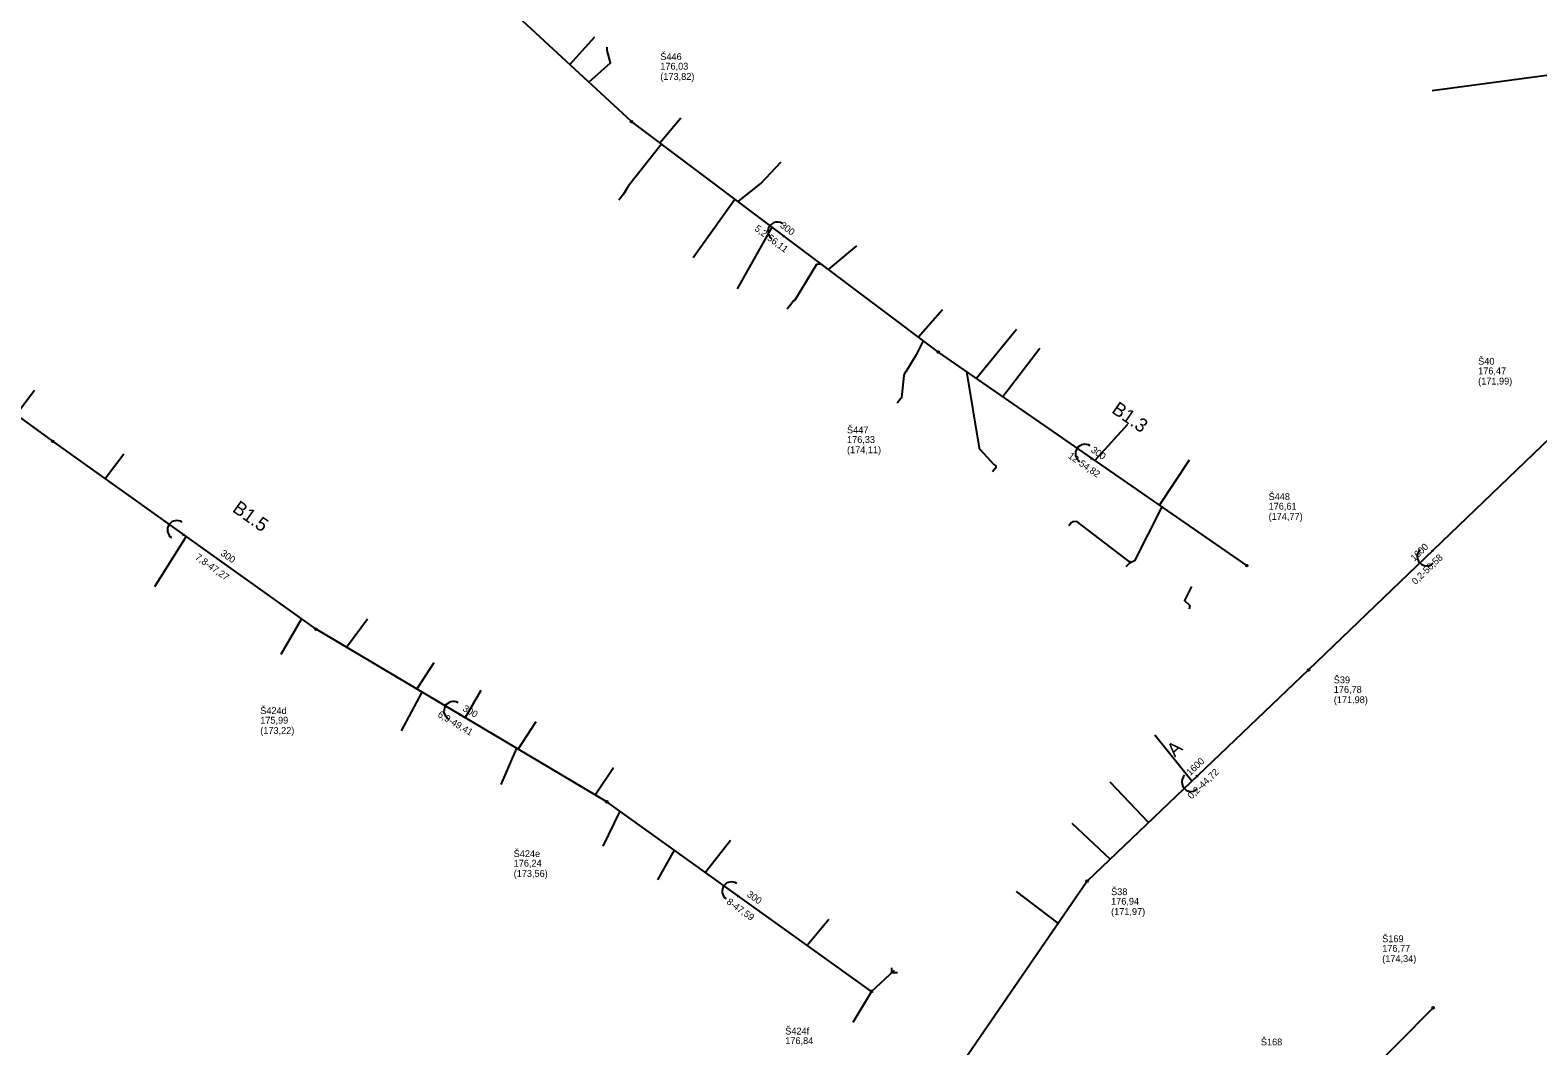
# Model space of a CAD drawing. Extents: x -548529 to -543591, y -1201432 to -1192608.
# Drawn here: x -544687.6 to -544467.3, y -1193181.6 to -1193033.2 of the extents above; entities that cross this region are included whole.
import ezdxf

# ---------------------------------------------------------------- set-up
doc = ezdxf.new("R2010")
doc.units = 0
for name, color, linetype in [('C3D_Bod-Značky', 7, 'Continuous'), ('C3D_Koridor', 7, 'Continuous'), ('C3D_Křižovatka', 7, 'Continuous'), ('C3D_Netisknutelná', 7, 'Continuous'), ('C3D_PP-zobrazeni v PR', 7, 'Continuous'), ('C3D_PR-Popisek', 7, 'Continuous'), ('C3D_SPR-Popisek', 7, 'Continuous'), ('C3D_Tlakove_potrubi_Popis', 7, 'Continuous'), ('C3D_ZPR-Formaty', 7, 'Continuous')]:
    doc.layers.add(name, color=color, linetype=linetype)

# ---------------------------------------------------------------- blocks, each defined once
blk = doc.blocks.new('100')
at = {"layer": 'Defpoints'}
blk.add_circle((0, 0), 0.127, dxfattribs=at)
blk = doc.blocks.new('91')
at = {"layer": 'Defpoints'}
blk.add_lwpolyline([(0.08, 0.14), (0.19, 0), (0.08, -0.14)], dxfattribs=at)
blk.add_arc((1.37, 0), 1.37, 270, 90, dxfattribs=at)

msp = doc.modelspace()

# ---------------------------------------------------------------- linework, layer by layer
at = {"layer": 'C3D_Bod-Značky'}
for points in [[(-544599.74, -1193046.54), (-544648.06, -1193001.85)], [(-544554.87, -1193080.23), (-544599.74, -1193046.54)], [(-544684.29, -1193093.27), (-544727.17, -1193062.03)], [(-544509.8, -1193111.44), (-544554.87, -1193080.23)], [(-544645.82, -1193120.74), (-544684.29, -1193093.27)], [(-544464.291, -1193091.64), (-544500.765, -1193126.682)], [(-544603.33, -1193145.96), (-544645.82, -1193120.74)], [(-544500.765, -1193126.682), (-544533.129, -1193157.543)], [(-544564.63, -1193173.66), (-544603.33, -1193145.96)], [(-544533.129, -1193157.543), (-544575.082, -1193218.62)], [(-544482.566, -1193176.062), (-544498.256, -1193191.91)]]:
    msp.add_lwpolyline(points, dxfattribs=at)
at = {"layer": 'C3D_Koridor'}
for points in [[(-544608.748, -1193038.209), (-544605.076, -1193034.138)], [(-544605.957, -1193040.79), (-544602.81, -1193037.965), (-544603.28, -1193036.152), (-544603.255, -1193035.67)], [(-544460.152, -1193039.016), (-544482.684, -1193042.051)], [(-544595.59, -1193049.656), (-544592.531, -1193045.973)], [(-544595.334, -1193049.848), (-544600.16, -1193055.92)], [(-544584.154, -1193058.242), (-544580.83, -1193055.57), (-544577.861, -1193052.437)], [(-544600.16, -1193055.92), (-544600.87, -1193057.14), (-544601.577, -1193058.049)], [(-544584.602, -1193057.906), (-544590.733, -1193066.461)], [(-544579.204, -1193061.959), (-544584.3, -1193070.962)], [(-544570.952, -1193068.155), (-544566.769, -1193064.702)], [(-544572.015, -1193067.357), (-544572.7, -1193067.43), (-544575.85, -1193072.65)], [(-544575.85, -1193072.65), (-544576.09, -1193072.8), (-544576.28, -1193073.07), (-544576.63, -1193073.51), (-544576.98, -1193073.97)], [(-544557.805, -1193078.026), (-544554.281, -1193073.989)], [(-544549.328, -1193084.068), (-544543.432, -1193076.86)], [(-544557.077, -1193078.573), (-544558.14, -1193080.61), (-544559.64, -1193083.12), (-544559.81, -1193083.35)], [(-544545.472, -1193086.738), (-544540.02, -1193079.651)], [(-544559.81, -1193083.35), (-544559.94, -1193083.63), (-544560.26, -1193086.91), (-544560.35, -1193087.01), (-544560.891, -1193087.694)], [(-544550.753, -1193083.085), (-544548.89, -1193094.27)], [(-544689.665, -1193089.354), (-544686.981, -1193085.778)], [(-544532.022, -1193096.052), (-544527.177, -1193090.745)], [(-544676.662, -1193098.717), (-544673.901, -1193095.117)], [(-544548.89, -1193094.27), (-544548.77, -1193094.48), (-544546.79, -1193096.66)], [(-544522.568, -1193102.599), (-544518.155, -1193095.988)], [(-544546.79, -1193096.66), (-544546.46, -1193096.84), (-544546.46, -1193097.05), (-544546.49, -1193097.15), (-544546.965, -1193097.744)], [(-544522.224, -1193102.838), (-544526.21, -1193110.74), (-544526.59, -1193110.95)], [(-544526.59, -1193110.95), (-544526.98, -1193110.81), (-544534.64, -1193105.01), (-544535.25, -1193105.04), (-544535.4, -1193105.15), (-544535.79, -1193105.611)], [(-544664.785, -1193107.198), (-544669.433, -1193114.52)], [(-544526.59, -1193110.95), (-544527.05, -1193111.17), (-544527.497, -1193111.63)], [(-544517.89, -1193114.48), (-544518.89, -1193116.54), (-544518.12, -1193117.24), (-544518.201, -1193117.804)], [(-544647.937, -1193119.229), (-544650.986, -1193124.403)], [(-544641.392, -1193123.368), (-544638.31, -1193119.191)], [(-544631.085, -1193129.486), (-544628.546, -1193125.611)], [(-544630.345, -1193129.925), (-544633.388, -1193135.583)], [(-544624.035, -1193133.671), (-544621.672, -1193129.656)], [(-544616.293, -1193138.266), (-544613.632, -1193134.216)], [(-544517.807, -1193142.933), (-544523.233, -1193136.216)], [(-544616.533, -1193138.123), (-544618.813, -1193143.429)], [(-544605.028, -1193144.952), (-544602.355, -1193140.936)], [(-544524.14, -1193148.971), (-544529.748, -1193143.066)], [(-544601.433, -1193147.318), (-544603.906, -1193152.458)], [(-544529.786, -1193154.355), (-544535.295, -1193149.111)], [(-544593.488, -1193153.005), (-544595.928, -1193157.372)], [(-544588.931, -1193156.266), (-544585.265, -1193151.538)], [(-544537.367, -1193163.713), (-544543.439, -1193159.078)], [(-544574.059, -1193166.911), (-544570.89, -1193163.11)], [(-544564.63, -1193173.66), (-544561.27, -1193170.547)], [(-544561.674, -1193170.922), (-544561.689, -1193170.232)], [(-544561.674, -1193170.922), (-544560.827, -1193170.88)], [(-544564.63, -1193173.66), (-544567.366, -1193178.226)]]:
    msp.add_lwpolyline(points, dxfattribs=at)

# ---------------------------------------------------------------- block references
at = {"layer": 'C3D_PP-zobrazeni v PR'}
for p, xscale, yscale, rotation in [((-544599.74, -1193046.54), 1.000000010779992, 1.0000000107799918, 141.00000108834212), ((-544554.87, -1193080.23), 1.000000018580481, 1.000000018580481, 144.99999976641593), ((-544684.29, -1193093.27), 1.000000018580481, 1.000000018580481, 144.99999976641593), ((-544509.8, -1193111.44), 0.9999999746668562, 0.999999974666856, -34.00000045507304), ((-544645.82, -1193120.74), 0.9999999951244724, 0.9999999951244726, 146.99999872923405), ((-544500.765, -1193126.682), 1.0000000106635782, 1.0000000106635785, -135.99999834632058), ((-544603.33, -1193145.96), 0.9999999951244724, 0.9999999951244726, 146.99999872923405), ((-544533.129, -1193157.543), 1.0000000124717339, 1.0000000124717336, -130.0000013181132), ((-544564.63, -1193173.66), 1.000000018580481, 1.000000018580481, -35.000000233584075), ((-544482.566, -1193176.062), 1.0000000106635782, 1.0000000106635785, 45.99999834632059)]:
    msp.add_blockref('100', p, dxfattribs=dict(at, xscale=xscale, yscale=yscale, rotation=rotation))
at = {"layer": 'C3D_SPR-Popisek'}
for p, xscale, yscale, rotation in [((-544577.305, -1193063.385), 1.000000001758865, 1.000000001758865, 144.00000066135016), ((-544532.335, -1193095.835), 0.9999999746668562, 0.999999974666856, 145.99999954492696), ((-544665.055, -1193107.005), 1.000000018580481, 1.000000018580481, 144.99999976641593), ((-544482.528, -1193109.161), 1.0000000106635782, 1.0000000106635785, -135.99999834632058), ((-544624.575, -1193133.35), 0.9999999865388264, 0.9999999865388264, 149.99999955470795), ((-544516.947, -1193142.112), 1.0000000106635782, 1.0000000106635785, -135.99999834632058), ((-544583.98, -1193159.81), 1.000000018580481, 1.000000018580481, 144.99999976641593)]:
    msp.add_blockref('91', p, dxfattribs=dict(at, xscale=xscale, yscale=yscale, rotation=rotation))

# ---------------------------------------------------------------- texts
at = {"layer": 'C3D_Křižovatka'}
for s, p in [('Š446', (-544595.51, -1193037.55)), ('Š40', (-544475.981, -1193082.07)), ('Š447', (-544568.22, -1193092.11)), ('Š448', (-544506.61, -1193101.85)), ('Š39', (-544497.085, -1193128.632)), ('Š424d', (-544653.98, -1193133.13)), ('Š424e', (-544616.94, -1193154.03)), ('Š38', (-544529.629, -1193159.593)), ('Š169', (-544490.006, -1193166.472)), ('Š424f', (-544577.25, -1193179.96)), ('Š168', (-544507.736, -1193181.55))]:
    msp.add_text(s, height=1, dxfattribs=at).set_placement(p)
at = {"layer": 'C3D_Netisknutelná'}
for s, rotation, p in [('B1.3', 325.3, (-544529.686, -1193088.984)), ('B1.5', 324.47, (-544658.182, -1193103.431)), ('A', 43.64, (-544520.318, -1193139.506))]:
    msp.add_text(s, height=2, rotation=rotation, dxfattribs=at).set_placement(p)
at = {"layer": 'C3D_PR-Popisek'}
for s, rotation, p in [('300', 323.1, (-544578.105, -1193061.908)), ('300', 325.3, (-544532.668, -1193094.757)), ('300', 324.47, (-544659.87, -1193109.845)), ('1600', 43.85, (-544485.309, -1193110.859)), ('300', 329.31, (-544624.482, -1193132.588)), ('1600', 43.64, (-544518.047, -1193142.191)), ('300', 324.41, (-544582.945, -1193159.688))]:
    msp.add_text(s, height=1, rotation=rotation, dxfattribs=at).set_placement(p)
at = {"layer": 'C3D_Tlakove_potrubi_Popis'}
for s, p in [('176,03 ', (-544595.51, -1193038.95)), ('(173,82)', (-544595.51, -1193040.45)), ('176,47 ', (-544475.981, -1193083.47)), ('(171,99)', (-544475.981, -1193084.97)), ('176,33 ', (-544568.22, -1193093.51)), ('(174,11)', (-544568.22, -1193095.01)), ('176,61 ', (-544506.61, -1193103.25)), ('(174,77)', (-544506.61, -1193104.75)), ('176,78 ', (-544497.085, -1193130.032)), ('(171,98)', (-544497.085, -1193131.532)), ('(173,22)', (-544653.98, -1193136.03)), ('175,99 ', (-544653.98, -1193134.53)), ('176,24 ', (-544616.94, -1193155.43)), ('(173,56)', (-544616.94, -1193156.93)), ('(171,97)', (-544529.629, -1193162.493)), ('176,94 ', (-544529.629, -1193160.993)), ('(174,34)', (-544490.006, -1193169.372)), ('176,77 ', (-544490.006, -1193167.872)), ('176,84 ', (-544577.25, -1193181.36))]:
    msp.add_text(s, height=1, dxfattribs=at).set_placement(p)
at = {"layer": 'C3D_ZPR-Formaty'}
for s, rotation, p in [('5,2-56,11', 323.1, (-544581.825, -1193062.367)), ('12-54,82', 325.3, (-544535.995, -1193095.617)), ('7,8-47,27', 324.47, (-544663.581, -1193110.395)), ('0,2-50,58', 43.85, (-544485.131, -1193114.287)), ('6,9-49,41', 329.31, (-544628.138, -1193133.444)), ('0,2-44,72', 43.64, (-544517.879, -1193145.627)), ('8-47,59', 324.41, (-544585.924, -1193160.759))]:
    msp.add_text(s, height=1, rotation=rotation, dxfattribs=at).set_placement(p)

doc.saveas('drawing.dxf')
